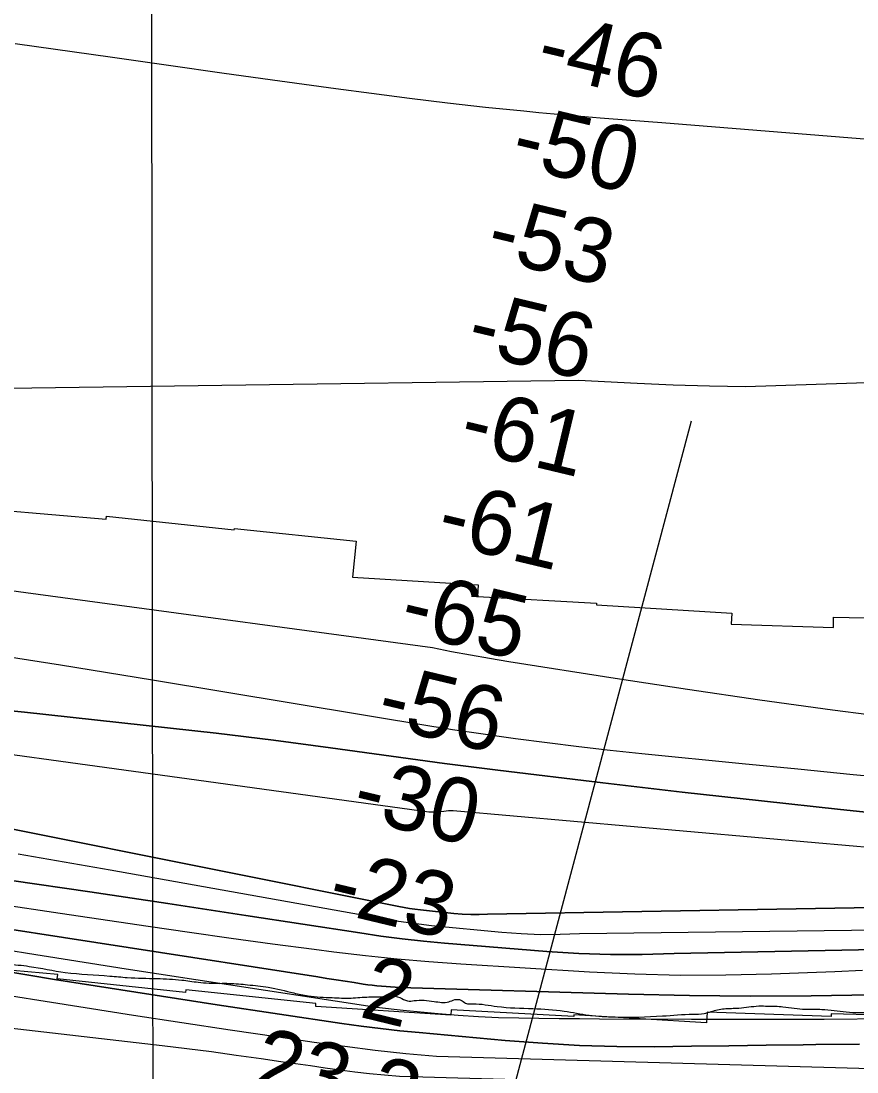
# Model space of a CAD drawing. Extents: x 3297772 to 3335630, y 634068 to 659439.
# Drawn here: x 3322784 to 3323655, y 645313 to 646409 of the extents above; entities that cross this region are included whole.
import ezdxf

# ---------------------------------------------------------------- set-up
doc = ezdxf.new("R2010")
doc.units = 0
for name, color, linetype in [('V-GRID-MAJR', 7, 'Continuous'), ('V-RIVR-EDGE', 7, 'Continuous'), ('V-RIVR-RANG', 7, 'Continuous'), ('V-RRAP-RVMT', 7, 'Continuous'), ('V-TOPO-DPTH', 7, 'Continuous'), ('V-TOPO-MAJR', 7, 'Continuous'), ('V-TOPO-MINR', 7, 'Continuous'), ('V-TOPO-WATR', 7, 'Continuous')]:
    doc.layers.add(name, color=color, linetype=linetype)

msp = doc.modelspace()

# ---------------------------------------------------------------- linework, layer by layer
at = {"layer": 'V-GRID-MAJR'}
msp.add_spline([(3322928.3, 639468), (3322924.7, 642495.6), (3322917.7, 648556.9), (3322910.6, 654618.3), (3322907.1, 657652)], degree=3, dxfattribs=at)
at = {"layer": 'V-RIVR-EDGE'}
msp.add_spline([(3321122.9, 645812.2), (3321138.4, 645807.6), (3321145.4, 645808.7), (3321149.8, 645810.5), (3321155.3, 645810.5), (3321158.9, 645809), (3321164.7, 645803.9), (3321170.6, 645800.9), (3321175.3, 645800.9), (3321179, 645800.9), (3321185.2, 645800.9), (3321214.4, 645789.5), (3321242.5, 645780.6), (3321282.7, 645770.7), (3321301, 645765.1), (3321304.3, 645767), (3321306.9, 645768.4), (3321313.4, 645768), (3321317.4, 645764), (3321319.3, 645761.8), (3321341.9, 645758.1), (3321355.1, 645756.2), (3321364.9, 645752.6), (3321386.9, 645746.3), (3321408, 645739.7), (3321426.7, 645734.1), (3321431.1, 645733.7), (3321446, 645730.8), (3321501.6, 645723.7), (3321519.8, 645719.6), (3321538.9, 645719.6), (3321562.6, 645714.8), (3321579.4, 645708.9), (3321585.6, 645702.7), (3321591.8, 645701.5), (3321625.1, 645693.8), (3321641.9, 645691.2), (3321653.9, 645689), (3321666.7, 645688.6), (3321679.5, 645688.2), (3321688.7, 645687.8), (3321698.9, 645686.3), (3321725.9, 645677.1), (3321747.1, 645672.3), (3321767.2, 645667.5), (3321793.1, 645657.6), (3321806.6, 645651.7), (3321827.5, 645645.4), (3321843.9, 645643.2), (3321857.4, 645639.1), (3321868, 645635.1), (3321887, 645631.4), (3321909.7, 645623.3), (3321931.2, 645618.8), (3321956.8, 645609.6), (3321991.8, 645598.9), (3322021.1, 645592.3), (3322042.3, 645586.4), (3322071.8, 645576.1), (3322089.7, 645568.7), (3322115.3, 645562.8), (3322126.3, 645561.3), (3322128.5, 645561.3), (3322128.5, 645563.5), (3322120.8, 645573.8), (3322119.4, 645578.5), (3322120.1, 645580.3), (3322121.9, 645580.7), (3322159.2, 645570.4), (3322191, 645559.7), (3322216.2, 645550.5), (3322238.1, 645543.5), (3322253.1, 645536.9), (3322274.6, 645531), (3322294.3, 645522.9), (3322303.1, 645518.1), (3322317, 645515.5), (3322329.8, 645511.5), (3322336.3, 645508.2), (3322351.7, 645502.6), (3322379.1, 645494.2), (3322394, 645492.7), (3322401.4, 645492.3), (3322413.8, 645483.5), (3322428.4, 645478.7), (3322445.2, 645476.1), (3322459.4, 645472.8), (3322468.6, 645470.5), (3322479.2, 645468), (3322500.7, 645466.4), (3322517.2, 645462.4), (3322539.1, 645458.3), (3322587.7, 645446.5), (3322615.4, 645438.4), (3322629.7, 645437.2), (3322656.7, 645432.1), (3322669.2, 645431.7), (3322686, 645432.7), (3322709, 645429.4), (3322741.5, 645426.7), (3322769.7, 645425.6), (3322792.3, 645423.3), (3322830, 645417), (3322876.4, 645413.2), (3322894.6, 645411.7), (3322925.7, 645410.6), (3322951.3, 645409), (3322968.5, 645406.8), (3322991.1, 645405.6), (3323001, 645405.6), (3323020, 645404.1), (3323041.6, 645401.5), (3323068.2, 645395.6), (3323083.2, 645392.6), (3323108.1, 645390.7), (3323127.8, 645390.3), (3323146.5, 645391.4), (3323158.5, 645391.7), (3323178.6, 645390.9), (3323186.7, 645387.3), (3323193.6, 645387.6), (3323214.4, 645386.8), (3323229.8, 645386.4), (3323236, 645388.6), (3323242.2, 645388.2), (3323247.3, 645384.9), (3323255, 645384.2), (3323280.2, 645381.5), (3323317.5, 645379.3), (3323350, 645376.6), (3323376, 645372.5), (3323403, 645370.6), (3323452.4, 645371.6), (3323484.2, 645373.4), (3323495.9, 645374.1), (3323503.2, 645376.2), (3323516.7, 645379.1), (3323532.1, 645379.8), (3323552.9, 645382), (3323562.4, 645381.9), (3323570.1, 645381.9), (3323578.1, 645381.2), (3323601.5, 645378.6), (3323618.7, 645378.5), (3323643.9, 645375.9), (3323672.1, 645375.5), (3323701, 645377.9), (3323726.5, 645375.7), (3323756.5, 645372.7), (3323766, 645373.4), (3323779.6, 645376.3), (3323798.2, 645378.1), (3323820.9, 645378), (3323843.9, 645377.6), (3323868.7, 645376.1), (3323894.3, 645374.5), (3323916.3, 645374.1), (3323941.9, 645375.5), (3323966.4, 645379.1), (3323979.5, 645379.8), (3323990.5, 645379.8), (3324002.2, 645376.5), (3324019.7, 645365.8), (3324029.2, 645363.6), (3324041.6, 645364.3), (3324055.9, 645368.3), (3324070.1, 645367.5), (3324089.5, 645365.3), (3324122.8, 645364.5), (3324137.4, 645363), (3324149.5, 645362.9), (3324171, 645363.3), (3324183.1, 645363.2), (3324194.4, 645360.6), (3324212.3, 645360.6), (3324227.3, 645361.3), (3324239.7, 645362.7), (3324254, 645362.3), (3324275.2, 645359.7), (3324284.7, 645360), (3324298.6, 645360.7), (3324315.8, 645361.4), (3324339.5, 645360.6), (3324360.7, 645361), (3324392.9, 645360.9), (3324417, 645359.4), (3324435.3, 645362.2), (3324454, 645360.4), (3324475.5, 645357.7), (3324498.9, 645357.3), (3324531.4, 645356.1), (3324558.5, 645357.2), (3324596.1, 645356.4), (3324618.4, 645355.2), (3324646.6, 645353.7), (3324666, 645355.8), (3324683.5, 645353.9), (3324697.7, 645350.6), (3324711.3, 645349.5), (3324734.7, 645348.3), (3324754, 645346.5), (3324777.1, 645345.3), (3324800.8, 645341.6), (3324818.4, 645343), (3324834.1, 645344.8), (3324855.3, 645346.9), (3324875.4, 645346.2), (3324888.9, 645343.2), (3324907.6, 645342.1), (3324921.8, 645341.7), (3324946.7, 645338.3), (3324963.1, 645338.6), (3324989.1, 645337.5), (3325010.6, 645335.2), (3325034.7, 645334.1), (3325053, 645333.7), (3325072.8, 645334.7), (3325094, 645337.9), (3325121.8, 645343.4), (3325141.5, 645350.6), (3325171.9, 645358.2), (3325196.8, 645366.6)], degree=3, dxfattribs=at)
at = {"layer": 'V-RIVR-RANG'}
msp.add_line((3323184, 644871), (3323482.9, 645991.8), dxfattribs=at)
at = {"layer": 'V-RRAP-RVMT'}
for p, q in [((3322742.2, 645900.7), (3322872.5, 645889.3)), ((3322872.5, 645889.3), (3322872.9, 645892.4)), ((3322872.9, 645892.4), (3323006, 645878.3)), ((3323006, 645878.3), (3323006.2, 645879.8)), ((3323006.2, 645879.8), (3323133.3, 645866.5)), ((3323133.3, 645866.5), (3323129.2, 645829)), ((3323129.2, 645829), (3323260.3, 645820.8)), ((3323260.3, 645820.8), (3323259.6, 645808.8)), ((3323259.6, 645808.8), (3323383.7, 645801.9)), ((3323383.7, 645801.9), (3323383.6, 645800)), ((3323383.6, 645800), (3323524.8, 645791.4)), ((3323524.8, 645791.4), (3323524.2, 645780.1)), ((3323630.9, 645776.3), (3323630.9, 645787.4)), ((3323630.9, 645787.4), (3323772.9, 645783.4)), ((3323524.2, 645780.1), (3323630.9, 645776.3)), ((3322822.1, 645414.9), (3322700.7, 645425.7)), ((3322821.5, 645410.3), (3322822.1, 645414.9)), ((3322955.4, 645396), (3322821.5, 645410.3)), ((3322955.7, 645398.9), (3322955.4, 645396)), ((3323091.2, 645384.6), (3322955.7, 645398.9)), ((3323091, 645381.4), (3323091.2, 645384.6)), ((3323231.7, 645372.4), (3323091, 645381.4)), ((3323232.2, 645378.1), (3323231.7, 645372.4)), ((3323360.1, 645371.1), (3323232.2, 645378.1)), ((3323498.4, 645364.4), (3323360.1, 645372.9)), ((3323360.1, 645372.9), (3323360.1, 645371.1)), ((3323499.2, 645375.7), (3323498.4, 645364.4)), ((3323628.3, 645370.9), (3323499.2, 645375.7)), ((3323628.4, 645373.9), (3323628.3, 645370.9)), ((3323761.3, 645370.2), (3323628.4, 645373.9))]:
    msp.add_line(p, q, dxfattribs=at)
at = {"layer": 'V-TOPO-DPTH'}
for points in [[(3322391, 645696.8), (3323209, 645584.4), (3323213, 645584.3), (3323217, 645584.5), (3323221.1, 645584.8), (3323224.7, 645585.2), (3323229.4, 645585.6), (3323234.2, 645585.9), (3323611.8, 645552.5), (3323674.8, 645546.7), (3323737.9, 645541), (3323800.9, 645535.5), (3323864, 645530), (3323941.8, 645523.4), (3323966, 645521.5), (3323990.2, 645519.7), (3324014.4, 645518.3), (3324038.6, 645517), (3324164, 645511.2), (3324250.9, 645507.7), (3324337.9, 645505), (3324424.9, 645503.5), (3324511.9, 645502.8), (3324823.7, 645502.5)], [(3322391, 645696.8), (3323209, 645584.4), (3323213, 645584.3), (3323217, 645584.5), (3323221.1, 645584.8), (3323224.7, 645585.2), (3323229.4, 645585.6), (3323234.2, 645585.9), (3323611.8, 645552.5), (3323674.8, 645546.7), (3323737.9, 645541), (3323800.9, 645535.5), (3323864, 645530), (3323941.8, 645523.4), (3323966, 645521.5), (3323990.2, 645519.7), (3324014.4, 645518.3), (3324038.6, 645517), (3324164, 645511.2), (3324250.9, 645507.7), (3324337.9, 645505), (3324424.9, 645503.5), (3324511.9, 645502.8), (3324823.7, 645502.5)], [(3323721, 645578.2), (3323638.2, 645586.8), (3323555.6, 645595.7), (3323472.9, 645605), (3323390.3, 645614.7), (3323281, 645627.8), (3323253.1, 645631.2), (3323225.2, 645634.7), (3323197.4, 645638.4), (3323169.5, 645642.2), (3323106.4, 645651), (3323046.9, 645658.9), (3322987.4, 645666.5), (3322787.5, 645688.1), (3322738, 645693)], [(3323721, 645578.2), (3323638.2, 645586.8), (3323555.6, 645595.7), (3323472.9, 645605), (3323390.3, 645614.7), (3323281, 645627.8), (3323253.1, 645631.2), (3323225.2, 645634.7), (3323197.4, 645638.4), (3323169.5, 645642.2), (3323106.4, 645651), (3323046.9, 645658.9), (3322987.4, 645666.5), (3322787.5, 645688.1), (3322738, 645693)], [(3322573.9, 645606.7), (3323177.5, 645485.7), (3323183.1, 645484.7), (3323188.8, 645483.7), (3323194.5, 645482.9), (3323200.2, 645482.2), (3323235.1, 645478.5), (3323243.8, 645477.8), (3323252.6, 645477.4), (3323261.4, 645477.4), (3323270.2, 645477.8), (3323913.6, 645488.7), (3323931, 645487.3), (3323948.4, 645486), (3323965.8, 645484.8), (3323983.2, 645483.7), (3324000.7, 645482.8), (3324018.1, 645482), (3324403.1, 645466.3), (3324485.7, 645463.5), (3324568.4, 645461.6)], [(3324568.4, 645461.6), (3324485.7, 645463.5), (3324403.1, 645466.3), (3324018.1, 645482), (3324000.7, 645482.8), (3323983.2, 645483.7), (3323965.8, 645484.8), (3323948.4, 645486), (3323931, 645487.3), (3323913.6, 645488.7), (3323270.2, 645477.8), (3323261.4, 645477.4), (3323252.6, 645477.4), (3323243.8, 645477.8), (3323235.1, 645478.5), (3323200.2, 645482.2), (3323194.5, 645482.9), (3323188.8, 645483.7), (3323183.1, 645484.7), (3323177.5, 645485.7), (3322573.9, 645606.7)], [(3323901.5, 645445.4), (3323464.6, 645436.7), (3323431.4, 645435.7), (3323398.3, 645435.6), (3323365.2, 645436.8), (3323332.1, 645438.9), (3323225.4, 645447.6), (3323203.2, 645449.7), (3323181.1, 645452.1), (3323159, 645454.9), (3323136.9, 645458.1), (3323018.2, 645476.3), (3322936.9, 645488.7), (3322855.4, 645500.9), (3322774, 645512.8)], [(3322774, 645512.8), (3322855.4, 645500.9), (3322936.9, 645488.7), (3323018.2, 645476.3), (3323136.9, 645458.1), (3323159, 645454.9), (3323181.1, 645452.1), (3323203.2, 645449.7), (3323225.4, 645447.6), (3323332.1, 645438.9), (3323365.2, 645436.8), (3323398.3, 645435.6), (3323431.4, 645435.7), (3323464.6, 645436.7), (3323901.5, 645445.4)], [(3323670.9, 645393.6), (3323607.4, 645392.5), (3323543.9, 645392.1), (3323480.5, 645392.8), (3323417, 645394.2), (3323178.5, 645401.4), (3323173.8, 645401.6), (3323169, 645401.8), (3323164.3, 645402.2), (3323159.5, 645402.5), (3323154.8, 645403), (3323150, 645403.6), (3323145.3, 645404.2), (3323140.6, 645404.9), (3323131.1, 645406.4), (3323121.6, 645407.9), (3323112.2, 645409.3), (3323102.7, 645410.8), (3323093.2, 645412.3), (3322697.4, 645473.6)], [(3322697.4, 645473.6), (3323093.2, 645412.3), (3323102.7, 645410.8), (3323112.2, 645409.3), (3323121.6, 645407.9), (3323131.1, 645406.4), (3323140.6, 645404.9), (3323145.3, 645404.2), (3323150, 645403.6), (3323154.8, 645403), (3323159.5, 645402.5), (3323164.3, 645402.2), (3323169, 645401.8), (3323173.8, 645401.6), (3323178.5, 645401.4), (3323417, 645394.2), (3323480.5, 645392.8), (3323543.9, 645392.1), (3323607.4, 645392.5), (3323670.9, 645393.6)], [(3323657.9, 645342.3), (3323612.5, 645341.7), (3323599.3, 645341.5), (3323560.4, 645341), (3323521.6, 645340.5), (3323482.7, 645340), (3323443.8, 645339.6), (3323404.9, 645339.9), (3323366.1, 645340.9), (3323327.3, 645343.1), (3323288.5, 645346), (3323199, 645354.2), (3323178.7, 645356.2), (3323158.5, 645358.4), (3323138.3, 645361), (3323118.1, 645363.9), (3322988.4, 645383.3), (3322903.5, 645396.3), (3322818.6, 645409.7), (3322733.8, 645423.8)]]:
    msp.add_lwpolyline(points, dxfattribs=at)
at = {"layer": 'V-TOPO-MAJR'}
for points in [[(3322777.6, 646385.2), (3322879.2, 646370.7), (3322937.4, 646362.4), (3322995.5, 646354.2), (3323053.7, 646346.2), (3323111.9, 646338.2), (3323149, 646333.2), (3323188.7, 646328.1), (3323228.3, 646323.2), (3323268.1, 646318.9), (3323307.9, 646314.8), (3323323.5, 646313.3), (3323355.5, 646310.3), (3323387.5, 646307.5), (3323419.6, 646305.1), (3323451.7, 646302.8), (3324128, 646248.2)], [(3323709.3, 645617.6), (3323651.4, 645623), (3323593.5, 645628.7), (3323535.7, 645634.4), (3323431.1, 645644.8), (3323398.1, 645648.3), (3323365.2, 645652.1), (3323332.3, 645656.2), (3323299.4, 645660.6), (3323253.4, 645667), (3323243.5, 645668.4), (3323233.7, 645669.9), (3323223.9, 645671.4), (3323214.1, 645673), (3322920.8, 645721.6), (3322825, 645737.1), (3322729.2, 645752.1)]]:
    msp.add_lwpolyline(points, dxfattribs=at)
at = {"layer": 'V-TOPO-MINR'}
for points in [[(3322571.8, 646023.2), (3323364.8, 646034.3), (3323426.1, 646031.2), (3323463.7, 646029.5), (3323501.4, 646028.3), (3323539.1, 646027.5), (3324086.1, 646045.8)], [(3323705.3, 645680.7), (3323629.7, 645690.4), (3323554, 645700.7), (3323478.5, 645711.7), (3323403.1, 645723.2), (3323292.2, 645740.7), (3323272.3, 645744), (3323252.4, 645747.5), (3323232.6, 645751.2), (3323212.8, 645755.1), (3322441.7, 645859.5)], [(3322391, 645696.8), (3323209, 645584.4), (3323213, 645584.3), (3323217, 645584.5), (3323221.1, 645584.8), (3323224.7, 645585.2), (3323229.4, 645585.6), (3323234.2, 645585.9), (3323611.8, 645552.5), (3323674.8, 645546.7), (3323737.9, 645541), (3323800.9, 645535.5), (3323864, 645530), (3323941.8, 645523.4), (3323966, 645521.5), (3323990.2, 645519.7), (3324014.4, 645518.3), (3324038.6, 645517), (3324164, 645511.2), (3324250.9, 645507.7), (3324337.9, 645505), (3324424.9, 645503.5), (3324511.9, 645502.8), (3324823.7, 645502.5)], [(3322738, 645693), (3322787.5, 645688.1), (3322987.4, 645666.5), (3323046.9, 645658.9), (3323106.4, 645651), (3323169.5, 645642.2), (3323197.4, 645638.4), (3323225.2, 645634.7), (3323253.1, 645631.2), (3323281, 645627.8), (3323390.3, 645614.7), (3323472.9, 645605), (3323555.6, 645595.7), (3323638.2, 645586.8), (3323721, 645578.2)], [(3322573.9, 645606.7), (3323177.5, 645485.7), (3323183.1, 645484.7), (3323188.8, 645483.7), (3323194.5, 645482.9), (3323200.2, 645482.2), (3323235.1, 645478.5), (3323243.8, 645477.8), (3323252.6, 645477.4), (3323261.4, 645477.4), (3323270.2, 645477.8), (3323913.6, 645488.7), (3323931, 645487.3), (3323948.4, 645486), (3323965.8, 645484.8), (3323983.2, 645483.7), (3324000.7, 645482.8), (3324018.1, 645482), (3324403.1, 645466.3), (3324485.7, 645463.5), (3324568.4, 645461.6)], [(3322781, 645540.7), (3322876.9, 645523.8), (3323158.8, 645473.4), (3323172, 645471.2), (3323185.2, 645469.2), (3323198.5, 645467.5), (3323211.8, 645466), (3323284.9, 645458.9), (3323305.2, 645457.5), (3323325.5, 645456.6), (3323345.8, 645456.7), (3323366.1, 645457.5), (3323961.3, 645464.7)], [(3322774, 645512.8), (3322855.4, 645500.9), (3322936.9, 645488.7), (3323018.2, 645476.3), (3323136.9, 645458.1), (3323159, 645454.9), (3323181.1, 645452.1), (3323203.2, 645449.7), (3323225.4, 645447.6), (3323332.1, 645438.9), (3323365.2, 645436.8), (3323398.3, 645435.6), (3323431.4, 645435.7), (3323464.6, 645436.7), (3323901.5, 645445.4)], [(3322759.3, 645488.6), (3322824.8, 645478.9), (3322916.5, 645465.2), (3322959.6, 645459), (3323002.8, 645452.8), (3323046, 645446.9), (3323089.3, 645441.2), (3323109.8, 645438.5), (3323142.9, 645434.6), (3323175.9, 645431.1), (3323209.1, 645428.3), (3323242.2, 645425.9), (3323376.3, 645417.7), (3323423.7, 645415.5), (3323471.1, 645414.2), (3323518.6, 645414.4), (3323566, 645415.4), (3323603.8, 645416.9), (3323632.3, 645418), (3323660.9, 645419.3)], [(3322688, 645453.9), (3322790.7, 645437), (3322893.4, 645420.8), (3323145.3, 645382.2), (3323154.5, 645380.9), (3323163.7, 645379.7), (3323172.9, 645378.6), (3323182.1, 645377.7), (3323218.6, 645374.1), (3323239.6, 645372.4), (3323260.6, 645371), (3323281.6, 645370.1), (3323302.7, 645369.5), (3323323.7, 645369.2), (3323344.8, 645369), (3323365.9, 645368.8), (3323386.9, 645368.7), (3323482.9, 645368.2), (3323552, 645368.1), (3323621.1, 645368.3), (3323690.1, 645369.1)], [(3322733.8, 645423.8), (3322818.6, 645409.7), (3322903.5, 645396.3), (3322988.4, 645383.3), (3323118.1, 645363.9), (3323138.3, 645361), (3323158.5, 645358.4), (3323178.7, 645356.2), (3323199, 645354.2), (3323288.5, 645346), (3323327.3, 645343.1), (3323366.1, 645340.9), (3323404.9, 645339.9), (3323443.8, 645339.6), (3323482.7, 645340), (3323521.6, 645340.5), (3323560.4, 645341), (3323599.3, 645341.5), (3323612.5, 645341.7), (3323657.9, 645342.3)], [(3322613.3, 645417.9), (3322850.8, 645380.4), (3322901.1, 645372.5), (3322951.4, 645364.8), (3323001.8, 645357.2), (3323052.1, 645349.8), (3323089.4, 645344.4), (3323121.2, 645340), (3323153, 645336), (3323184.9, 645332.6), (3323216.8, 645329.6), (3323706.2, 645315.8)], [(3322753, 645361.4), (3322930.8, 645340.7), (3322956.7, 645337.6), (3322982.5, 645334.4), (3323008.2, 645330.9), (3323034, 645327.3), (3323054.7, 645324.3), (3323070.1, 645322.1), (3323085.5, 645319.9), (3323100.9, 645317.7), (3323116.3, 645315.5), (3323131.8, 645313.5), (3323147.2, 645311.6), (3323162.7, 645310.1), (3323178.2, 645308.7), (3323812.3, 645290.9)]]:
    msp.add_lwpolyline(points, dxfattribs=at)
at = {"layer": 'V-TOPO-WATR'}
msp.add_lwpolyline([(3322697.4, 645473.6), (3323093.2, 645412.3), (3323102.7, 645410.8), (3323112.2, 645409.3), (3323121.6, 645407.9), (3323131.1, 645406.4), (3323140.6, 645404.9), (3323145.3, 645404.2), (3323150, 645403.6), (3323154.8, 645403), (3323159.5, 645402.5), (3323164.3, 645402.2), (3323169, 645401.8), (3323173.8, 645401.6), (3323178.5, 645401.4), (3323417, 645394.2), (3323480.5, 645392.8), (3323543.9, 645392.1), (3323607.4, 645392.5), (3323670.9, 645393.6)], dxfattribs=at)

# ---------------------------------------------------------------- texts
at = {"layer": 'V-RIVR-RANG'}
for s, rotation, p in [('-46', 346.5734, (3323318.6, 646355.2)), ('-50', 346.5734, (3323292.3, 646258.6)), ('-53', 346.5734, (3323266.6, 646162)), ('-56', 346.5734, (3323246.2, 646064)), ('-61', 346.5734, (3323238.4, 645963.1)), ('-61', 346.5734, (3323214.9, 645865.9)), ('-65', 346.5734, (3323176.3, 645772.3)), ('-56', 346.5734, (3323152.3, 645675.2)), ('-30', 346.5734, (3323126.6, 645578.5)), ('-23', 346.5734, (3323101.3, 645481.7)), ('2', 346.2883, (3323135.2, 645371)), ('23.2', 346.2883, (3323021.3, 645295.8))]:
    msp.add_text(s, height=67, rotation=rotation, dxfattribs=at).set_placement(p)

doc.saveas('drawing.dxf')
